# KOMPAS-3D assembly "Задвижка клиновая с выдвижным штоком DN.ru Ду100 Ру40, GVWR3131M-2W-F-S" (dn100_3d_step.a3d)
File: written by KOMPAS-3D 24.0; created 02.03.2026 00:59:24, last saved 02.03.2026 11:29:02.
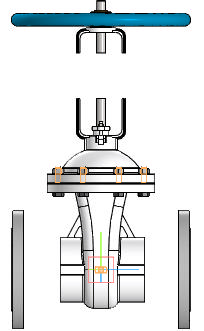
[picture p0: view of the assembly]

Document properties: Автор: R2D2; Полное имя файла: E:\Работа\Зайцев\GVWR3131M-2W-F-S Задвижка клиновая с выдвижным штоком DN.ru Ду50-100 Ру40\исходные материалы\DN100\dn100_3d_step.a3d

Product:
- Component [detail]: Деталь2  | qty 1  | pos. 1  | Масса: 5.406695; Автор: R2D2; additional columns: Типовые; source file: Деталь2 Деталь2.m3d
- Component [detail]: ANSI B18.2.4.2M - M5x0,8 - 8  | designation ANSI B18.2.4.2M - M5x0,8  | qty 2  | pos. 2  | Масса: 0.00167; Комментарий: Типы метрических   шестигранных гаек   2; Автор: R2D2; additional columns: Сталь, мягкая; source file: ANSI B18.2.4.2M - M5x0,8 ANSI B18.2.4.2M - M5x0,8 - 8.m3d
- Component [detail]: Деталь1  | qty 1  | pos. 3  | Масса: 36.799325; additional columns: Типовые; source file: 2.m3d
- Component [detail]: Деталь1  | qty 1  | pos. 3  | Масса: 0.571095; Автор: R2D2; additional columns: Типовые; source file: 3.m3d
- Component [detail]: Деталь1  | qty 2  | pos. 3  | Масса: 5.351688; Автор: R2D2; additional columns: Типовые; source file: 1.m3d
- Component [standard]: Болт М12-6gx50.88.45Г.019 ГОСТ 7798-70  | qty 8  | Материал: Сталь 45Г (density 7850 kg/m3); Масса: 0.06053; Раздел спецификации: Стандартные изделия; Рассекать на разрезах: no; additional columns: BOSimple***Material:39848d99-529e-4aa2-825c-393daa009d15
- Component [standard]: Гайка М12-6H ГОСТ 5915-70  | qty 24  | Масса: 0.0184; Раздел спецификации: Стандартные изделия; Рассекать на разрезах: no
- Part/product: Задвижка клиновая с выдвижным штоком DN.ru Ду100 Ру40  | designation GVWR3131M-2W-F-S
    Масса: 39
    Раздел спецификации: Прочие изделия
    Примечание: D040-09952

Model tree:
1. Массив по концентрической сетке:1  (labels: Грань.Твердое тело1)  (8 pattern instances)
     Шаг 2 = 360
2. Массив по концентрической сетке:2  (with: Грань.Элемент вращения:1)  (labels: Грань.Твердое тело1; Грань.Solid1)  (2 pattern instances)
     Шаг 2 = 360; Расстояние = -525; Расстояние = -175; Ориентация = 2

Referenced files in E:\Работа\Зайцев\GVWR3131M-2W-F-S Задвижка клиновая с выдвижным штоком DN.ru Ду50-100 Ру40\исходные материалы\DN100\: Деталь2 Деталь2.m3d, ANSI B18.2.4.2M - M5x0,8 ANSI B18.2.4.2M - M5x0,8 - 8.m3d, 2.m3d, 3.m3d, 1.m3d
Referenced files in C:\Program Files\ASCON\KOMPAS-3D v24\Libs\PolynomLib\DATA\vault\Methods\Kompas\3D\: PLib_Bolt_1_900.m3d, PLib_Nut_OST92_900.m3d
Referenced files in E:\Работа\Зайцев\GVWR3131M-2W-F-S Задвижка клиновая с выдвижным штоком DN.ru Ду50-200 Ру63\DN100\исходные материалы\: 1.m3d, ANSI B18.2.4.2M - M5x0,8 ANSI B18.2.4.2M - M5x0,8 - 8.m3d
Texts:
  ANSI B18.2.4.2M - M5x0,8
  Крепежное изделие ГОСТ
  BOSimple***PART:25ccc031-f2ed-a43b-e633-090566d53ffa***SHORTLOC:Root±30±20±10±80±10±©{}30±©{BASE}130±290[9;Цинковое, хроматированное;Сталь 45Г ГОСТ 4543-2016;50;12;19;1,75;8.8]
  BOSimple***Material:39848d99-529e-4aa2-825c-393daa009d15
  BOSimple***PART:dfaf85ed-3e43-003f-b29c-9c5b054070d3***SHORTLOC:Root±30±10±20±©{}110±10±50±60[Нет;Без покрытия;Без указания материала;-;12;1,75;19]
  Программные изделия  и базы данных
  GVWR3131M-2W-F-S
  Деталь2 Деталь2
  ANSI B18.2.4.2M - M5x0,8 ANSI B18.2.4.2M - M5x0,8 - 8 (1)
  Деталь1 Деталь1
  Деталь1 Деталь1 (1)
  Деталь1 Деталь1 (2)
  Болт М12-6gx50.88.45Г.019 ГОСТ 7798-70 (1)
  hole1
  hole2
  Гайка М12-6H ГОСТ 5915-70 (1)
  bcut1
  hcut1
  cut1
  Гайка М12-6H ГОСТ 5915-70 (2)
  Гайка М12-6H ГОСТ 5915-70 (3)
  Гайка М12-6H ГОСТ 5915-70 (4)
  Гайка М12-6H ГОСТ 5915-70 (5)
  Гайка М12-6H ГОСТ 5915-70 (6)
  Болт М12-6gx50.88.45Г.019 ГОСТ 7798-70 (2)
  Гайка М12-6H ГОСТ 5915-70 (7)
  Гайка М12-6H ГОСТ 5915-70 (8)
  Гайка М12-6H ГОСТ 5915-70 (9)
  Болт М12-6gx50.88.45Г.019 ГОСТ 7798-70 (3)
  Гайка М12-6H ГОСТ 5915-70 (10)
  Гайка М12-6H ГОСТ 5915-70 (11)
  Гайка М12-6H ГОСТ 5915-70 (12)
  Болт М12-6gx50.88.45Г.019 ГОСТ 7798-70 (4)
  Гайка М12-6H ГОСТ 5915-70 (13)
  Гайка М12-6H ГОСТ 5915-70 (14)
  Гайка М12-6H ГОСТ 5915-70 (15)
  Болт М12-6gx50.88.45Г.019 ГОСТ 7798-70 (5)
  Гайка М12-6H ГОСТ 5915-70 (16)
  Гайка М12-6H ГОСТ 5915-70 (17)
  Гайка М12-6H ГОСТ 5915-70 (18)
  Болт М12-6gx50.88.45Г.019 ГОСТ 7798-70 (6)
  Гайка М12-6H ГОСТ 5915-70 (19)
  Гайка М12-6H ГОСТ 5915-70 (20)
  Гайка М12-6H ГОСТ 5915-70 (21)
  Болт М12-6gx50.88.45Г.019 ГОСТ 7798-70 (7)
  Гайка М12-6H ГОСТ 5915-70 (22)
  Гайка М12-6H ГОСТ 5915-70 (23)
  Гайка М12-6H ГОСТ 5915-70 (24)
  Болт М12-6gx50.88.45Г.019 ГОСТ 7798-70 (8)
  ANSI B18.2.4.2M - M5x0,8 ANSI B18.2.4.2M - M5x0,8 - 8 (2)
  Ось Z.Начало координат
  Ось Y.Начало координат
  Плоскость ZX.Начало координат
  Плоскость XY.Начало координат
  Plane. Начало координат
